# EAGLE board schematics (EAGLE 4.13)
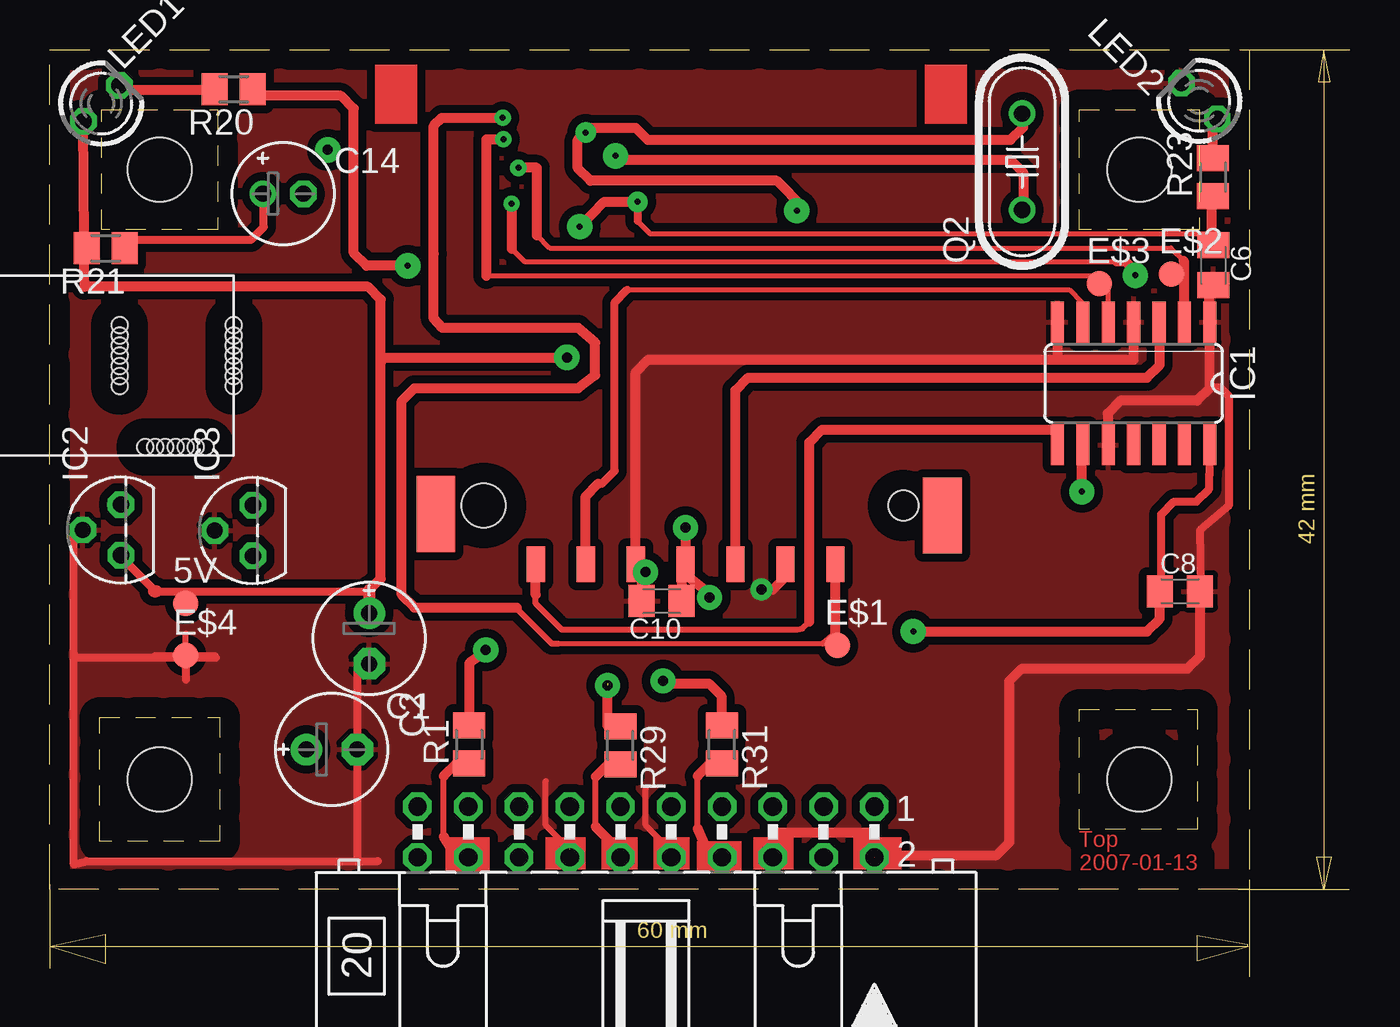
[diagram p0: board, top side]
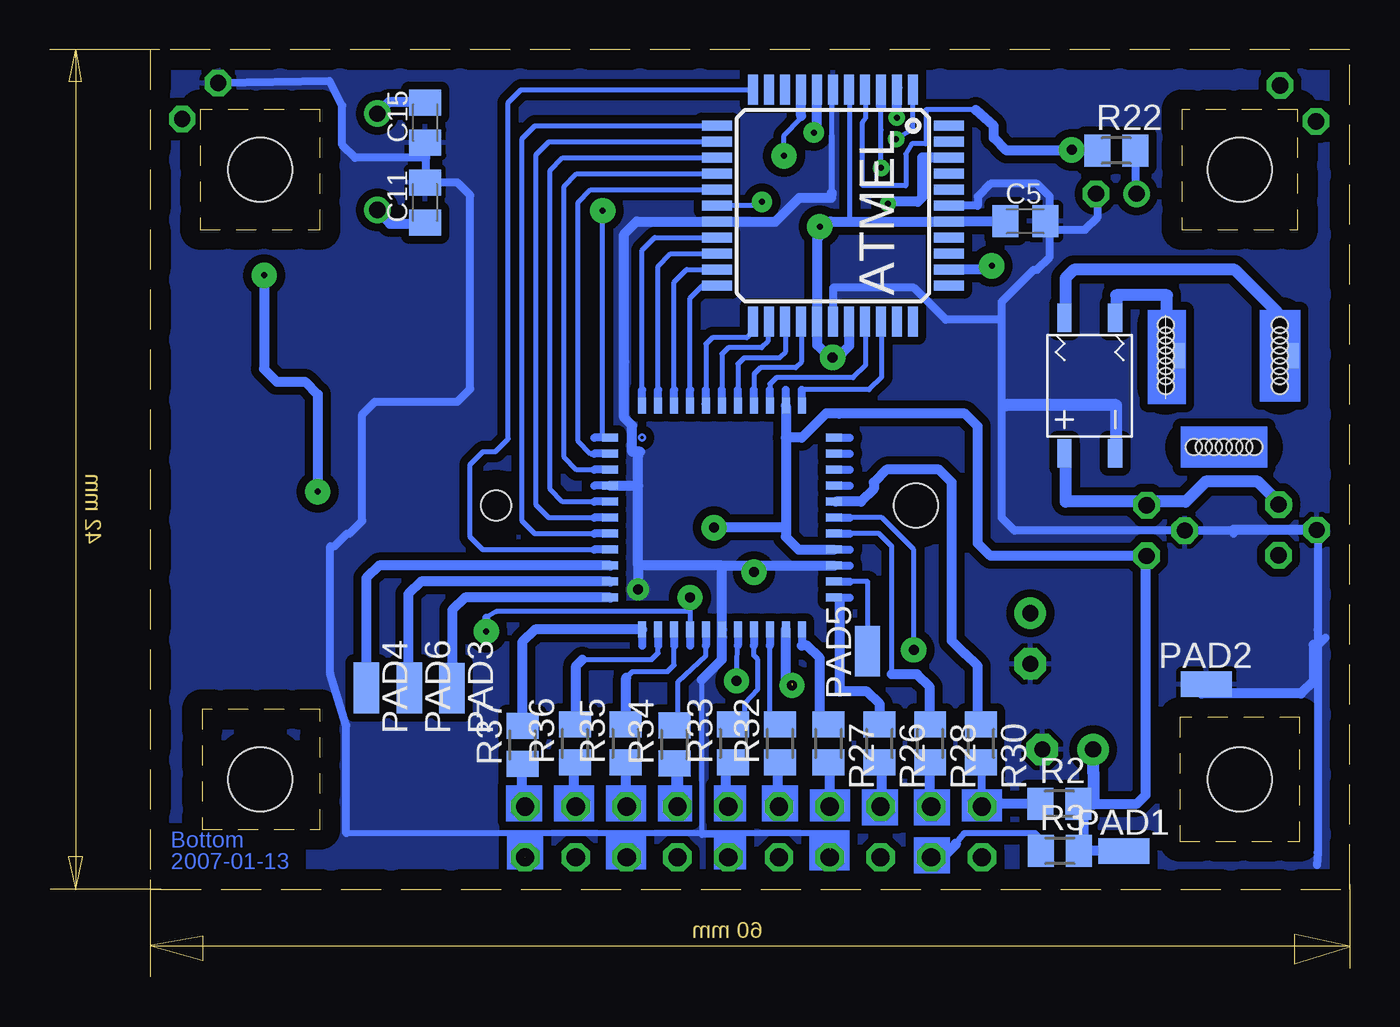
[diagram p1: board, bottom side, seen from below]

Size 65.03 x 46.38 mm. Coordinates in mm from the lower left corner, seen from the top.
Outline: 50 segments
Copper layers (1*16): Top 0.035mm / dielectric 1.5mm / Bottom 0.035mm
Design rules "default": minimum track width 10mil, minimum drill 24mil, track to track 8mil, track to pad 8mil, pad to pad 8mil, via to via 8mil, smd to smd 8mil, copper to edge 40mil, drill to drill 8mil, minimum pad ring 10mil, minimum via ring 8mil, stop-mask expansion 4mil, vias tented up to drill 0mil, thermal gap 10mil
Holes 3.2 mm at 5.5,40.38 54.5,40.38 54.5,9.88 5.5,9.88

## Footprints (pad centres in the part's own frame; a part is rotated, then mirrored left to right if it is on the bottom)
B1,27 = smd 1.27 x 1.27: PP 0,0
TQFP-44 = smd 1.5 x 0.5: 1 -5.8,4; 2 -5.8,3.2; 3 -5.8,2.4; 4 -5.8,1.6; 5 -5.8,0.8; 6 -5.8,0; 7 -5.8,-0.8; 8 -5.8,-1.6; 9 -5.8,-2.4; 10 -5.8,-3.2; 11 -5.8,-4; 23 5.8,-4; 24 5.8,-3.2; 25 5.8,-2.4; 26 5.8,-1.6; 27 5.8,-0.8; 28 5.8,0; 29 5.8,0.8; 30 5.8,1.6; 31 5.8,2.4; 32 5.8,3.2; 33 5.8,4 | smd 0.5 x 1.5: 12 -4,-5.8; 13 -3.2,-5.8; 14 -2.4,-5.8; 15 -1.6,-5.8; 16 -0.8,-5.8; 17 0,-5.8; 18 0.8,-5.8; 19 1.6,-5.8; 20 2.4,-5.8; 21 3.2,-5.8; 22 4,-5.8; 34 4,5.8; 35 3.2,5.8; 36 2.4,5.8; 37 1.6,5.8; 38 0.8,5.8; 39 0,5.8; 40 -0.8,5.8; 41 -1.6,5.8; 42 -2.4,5.8; 43 -3.2,5.8; 44 -4,5.8
E2,5-6E = drill 0.813 pad 1.575 round: + -1.27,0 | drill 0.813 pad 1.575 octagon: - 1.27,0
C0805K = smd 1.3 x 1.6: 1 -1,0; 2 1,0
E2-5 = drill 0.813 pad 1.27 round: + -1.016,0 | drill 0.813 pad 1.27 octagon: - 1.016,0
DC_CON = smd 1.27 x 0.635 bottom: IN 0,6.35; OUT 0,0.635 | hole 0.8: -0.508,0; -1.016,0; 0.508,0; 1.016,0; 1.524,0; -1.524,0; -0.508,5.715; -1.016,5.715; -1.524,5.715; 0.508,5.715; 1.016,5.715; 1.524,5.715; -4.572,3.937; -4.572,3.429; -4.572,4.445; -4.572,2.413; -4.572,1.905; -4.572,1.397; 0,5.715; -4.572,2.921; 0,0
SO14 = smd 0.66 x 2.032: 1 -3.81,-3.073; 2 -2.54,-3.073; 3 -1.27,-3.073; 4 0,-3.073; 5 1.27,-3.073; 6 2.54,-3.073; 7 3.81,-3.073; 8 3.81,3.073; 9 2.54,3.073; 10 1.27,3.073; 11 0,3.073; 12 -1.27,3.073; 13 -2.54,3.073; 14 -3.81,3.073
TO92 = drill 0.813 octagon: 1 -1.27,0; 2 0,1.905; 3 1.27,0
LED3MM = drill 0.813 octagon: A -1.27,0; K 1.27,0
MMC = smd 0.914 x 1.778: 3.3V 2,-25; CS -5.5,-25; GND -0.5,-25; GND1 7,-25; MISO 9.5,-25; MOSI -3,-25; SCK 4.5,-25 | smd 1.93 x 3.81: P$10 14.85,-22.57; P$11 -10.5,-22.5 | hole 2.2: -8.109,-22.071 | hole 1.5: 12.889,-22.071
SMD2 = smd 1.27 x 2.54: 1 0,0
HC49/S = drill 0.813 round: 1 -2.413,0; 2 2.413,0
M0805 = smd 1.3 x 1.6: 1 -0.95,0; 2 0.95,0
SMD_B40 = smd 1.422 x 0.711: + -3.387,1.27; - -3.387,-1.27; ~1 3.387,1.27; ~2 3.387,-1.27
ML20L = drill 0.914 octagon: 1 -11.43,-1.27; 2 -11.43,1.27; 3 -8.89,-1.27; 4 -8.89,1.27; 5 -6.35,-1.27; 6 -6.35,1.27; 7 -3.81,-1.27; 8 -3.81,1.27; 9 -1.27,-1.27; 10 -1.27,1.27; 11 1.27,-1.27; 12 1.27,1.27; 13 3.81,-1.27; 14 3.81,1.27; 15 6.35,-1.27; 16 6.35,1.27; 17 8.89,-1.27; 18 8.89,1.27; 19 11.43,-1.27; 20 11.43,1.27
VQ44 = smd 0.813 x 0.406: PIN$1 -5.6,4; PIN$2 -5.6,3.2; PIN$3 -5.6,2.4; PIN$4 -5.6,1.6; PIN$5 -5.6,0.8; PIN$6 -5.6,0; PIN$7 -5.6,-0.8; PIN$8 -5.6,-1.6; PIN$9 -5.6,-2.4; PIN$10 -5.6,-3.2; PIN$11 -5.6,-4; PIN$23 5.6,-4; PIN$24 5.6,-3.2; PIN$25 5.6,-2.4; PIN$26 5.6,-1.6; PIN$27 5.6,-0.8; PIN$28 5.6,0; PIN$29 5.6,0.8; PIN$30 5.6,1.6; PIN$31 5.6,2.4; PIN$32 5.6,3.2; PIN$33 5.6,4 | smd 0.406 x 0.813: PIN$12 -4,-5.6; PIN$13 -3.2,-5.6; PIN$14 -2.4,-5.6; PIN$15 -1.6,-5.6; PIN$16 -0.8,-5.6; PIN$17 0,-5.6; PIN$18 0.8,-5.6; PIN$19 1.6,-5.6; PIN$20 2.4,-5.6; PIN$21 3.2,-5.6; PIN$22 4,-5.6; PIN$34 4,5.6; PIN$35 3.2,5.6; PIN$36 2.4,5.6; PIN$37 1.6,5.6; PIN$38 0.8,5.6; PIN$39 0,5.6; PIN$40 -0.8,5.6; PIN$41 -1.6,5.6; PIN$42 -2.4,5.6; PIN$43 -3.2,5.6; PIN$44 -4,5.6

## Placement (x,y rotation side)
5V  [B1,27]  6.8,18.67 0 top
ATMEL  ATMEGA16-16AI  [TQFP-44]  25.84,38.59 270 bottom
C1  10 uF  [E2,5-6E]  14.1,11.37 0 top
C2  10 uF  [E2,5-6E]  15.97,16.92 270 top
C5  100 nF  [C0805K]  16.22,37.8 0 bottom
C6  100 nF  [C0805K]  58.22,35.6 270 top
C8  100 nF  [C0805K]  56.54,19.28 0 top
C10  100 nF  [C0805K]  30.6,18.8 180 top
C11  22 pF  [C0805K]  46.26,38.73 90 bottom
C14  10 uF  [E2-5]  11.67,39.18 0 top
C15  22 pF  [C0805K]  46.25,42.73 90 bottom
E$1  [B1,27]  39.4,16.58 0 top
E$2  [B1,27]  56.12,35.16 0 top
E$3  [B1,27]  52.5,34.67 0 top
E$4  [B1,27]  6.8,16.08 0 top
E$5  [DC_CON]  9.2,31.08 90 top
IC1  74LV125  [SO14]  54.22,29.69 180 top
IC2  LP2950 CZ-5.0  [TO92]  3.55,22.35 90 top
IC3  LP2950 CZ-3.3  [TO92]  10.15,22.33 90 top
LED1  [LED3MM]  2.57,43.7 45 top
LED2  [LED3MM]  57.51,43.82 135 top
MMC  [MMC]  29.8,45.65 0 top
PAD1  [SMD2]  11.29,6.29 270 bottom
PAD2  [SMD2]  7.17,14.63 270 bottom
PAD3  [SMD2]  44.91,14.44 180 bottom
PAD4  [SMD2]  49.19,14.46 180 bottom
PAD5  [SMD2]  24.12,16.28 0 bottom
PAD6  [SMD2]  47.05,14.45 180 bottom
Q2  16 MHz  [HC49/S]  48.65,40.78 90 top
R1  47  [M0805]  20.98,11.62 90 top
R2  10 k  [M0805]  14.51,8.66 0 bottom
R3  10 k  [M0805]  14.49,6.3 0 bottom
R20  120  [M0805]  9.19,44.41 180 top
R21  10k  [M0805]  2.78,36.45 180 top
R22  100  [M0805]  11.67,41.34 0 bottom
R23  1k8  [M0805]  58.19,40.01 90 top
R26  47  [M0805]  23.52,11.66 270 bottom
R27  47  [M0805]  26.06,11.66 270 bottom
R28  47  [M0805]  20.98,11.66 270 bottom
R29  47  [M0805]  28.54,11.59 270 top
R30  47  [M0805]  18.44,11.67 270 bottom
R31  47  [M0805]  33.62,11.62 270 top
R32  47  [M0805]  28.5,11.66 90 bottom
R33  47  [M0805]  30.84,11.67 90 bottom
R34  47  [M0805]  33.79,11.62 90 bottom
R35  47  [M0805]  36.22,11.67 90 bottom
R36  47  [M0805]  38.76,11.66 90 bottom
R37  47  [M0805]  41.38,11.6 90 bottom
RECT  [SMD_B40]  13,29.58 90 bottom
SV2  [ML20L]  29.82,7.24 180 top
XILINX  [VQ44]  31.4,22.98 0 bottom

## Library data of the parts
5V E$1-E$4 = testpad
ATMEL = Atmel_Prototype_Header
C1 C2 C5 C6 C8 C10 C11 C14 C15 R1-R3 R20-R23 R26-R37 = rcl
E$5 MMC RECT = jookie
IC1 = 74xx-eu
IC2 IC3 = linear
LED1 LED2 = led
PAD1-PAD6 = wirepad
Q2 = crystal
SV2 = con-harting-ml
XILINX = xilinx

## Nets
3.3V: C1.+ C8.1 C10.1 IC3.1 PAD1.1 R2.2 R3.2
5V: ATMEL.5 ATMEL.17 ATMEL.27 ATMEL.29 ATMEL.38 C2.+ C5.1 C6.1 LED1.A R21.2 R23.1
ACK: R1.2
AD0: R37.2
AD1: R36.2
AD2: R35.2
AD3: R34.2
AD4: R28.1
AD5: R26.1
AD6: R29.1
AD7: R32.2
CLK: ATMEL.7 C15.2 Q2.2
CS: IC1.8
CS1: ATMEL.42 IC1.9
DRQ: R31.1
GND: ATMEL.6 ATMEL.18 ATMEL.28 C1.- C2.- C5.2 C6.2 C8.2 C10.2 C11.2 C14.- C15.1 IC1.1 IC1.4 IC1.7 IC1.10 IC2.2 IC3.2 LED2.K PAD2.1 SV2.2 SV2.6 SV2.10 SV2.14
MISO: ATMEL.2
MOSI: IC1.6
MOSI1: ATMEL.1 IC1.5
N$1: ATMEL.35 R20.1
N$2: ATMEL.19
N$3: ATMEL.20
N$4: ATMEL.21
N$5: ATMEL.22
N$6: ATMEL.23
N$7: ATMEL.24
N$8: ATMEL.25
N$9: ATMEL.26
N$10: ATMEL.30
N$11: ATMEL.31
N$12: ATMEL.16
N$13: ATMEL.15
N$14: ATMEL.14
N$15: ATMEL.11
N$16: ATMEL.13
N$17: ATMEL.12
N$18: R27.2 SV2.13
N$19: R26.2 SV2.15
N$20: R28.2 SV2.17
N$21: R2.1 R30.2 SV2.19
N$22: R29.2 SV2.12
N$23: R31.2 SV2.8
N$24: R32.1 SV2.11
N$25: R33.1 SV2.9
N$26: R34.1 SV2.7
N$27: R35.1 SV2.5
N$28: R36.1 SV2.3
N$29: R37.1 SV2.1
N$31: ATMEL.10
N$32: ATMEL.9
N$33: C14.+ R21.1 R22.2
N$34: PAD3.1
N$35: PAD5.1
N$36: PAD4.1
N$37: PAD6.1
N$38: ATMEL.34
N$40: ATMEL.8 C11.1 Q2.1
N$44: LED2.A R23.2
N$47: LED1.K R20.2
N$50: R27.1
N$57: R1.1 R3.1 SV2.18
N$58: R30.1
N$61: ATMEL.39
RESET: ATMEL.4 R22.1
S$4: IC2.1
SCK: IC1.3
SCK1: ATMEL.3 IC1.2
URAW: IC2.3 IC3.3
VCC: IC1.14
WIREX: R33.2

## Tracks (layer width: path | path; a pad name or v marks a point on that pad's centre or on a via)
3.3V  (via drill 0.3 pad 1.27, 0.5 pad 0.41)
  Top 0.254: 31.8,20.59 31.83,20.59 31.83,20.58 31.6,20.58 | 33,19.17 v33,18.98 | 55.53,18.88 55.54,18.88 | 55.54,18.88 C8.1 55.6,19.28 | 55.54,18.88 55.73,18.88
  Top 0.406: 58.03,26.77 58.03,25.11 58,25.11 58,24.41 57.36,23.77 56.23,23.77 55.6,23.14 55.6,19.28
  Top 0.5: v31.8,22.48 31.8,20.59 | 31.83,20.59 32,19.98 33,19.17 33,18.88 | v43.2,17.27 54.89,17.27 55.53,17.91 55.53,18.88 | 31.6,20.58 C10.1
  Bottom 0.254: 28.2,26.98 28.2,28.58 28.19,28.56 28.2,28.56 | 25.8,21.38 25.8,21.37 25.79,21.37 | 28.2,22.58 28.2,22.48 | 33,17.37 33,16.98 | 33,17.37 32.99,17.37 | v33,18.98 33,18.27 | 33,18.27 33,17.37 | 13.3,7.07 13.3,7.09 R3.2 | 13.3,8.66 R2.2 | PAD1.1 11,6.09 11.2,6.3 11,5.98 | 10.2,21.05 10.2,21.08 | 33,18.27 42.7,18.27 43.2,17.98 | v43.2,17.27 43.1,17.08
  Bottom 0.406: 43.2,17.98 v43.2,17.27
  Bottom 0.5: 10.2,21.05 IC3.1 | 10.2,21.05 17.97,21.05 18.6,21.69 18.6,27.54 19.23,28.17 25.54,28.17 26.19,28.19 27.4,26.98 28.2,26.98 | 28.2,28.56 28.2,22.58 28.2,22.01 27.56,21.38 25.8,21.38 | 28.2,22.48 v31.8,22.48 | 13.3,7.09 13.3,8.66 | 11.2,6.3 R3.2 | R2.2 12.8,8.66 10.64,8.66 10.2,9.09 10.2,21.05
  Bottom 0.61: 12.8,8.66 12.8,10.17 12.83,10.2 C1.+
5V  (via drill 0.3 pad 1.02, 0.3 pad 1.27, 0.5 pad 1.27)
  Top 0.254: R23.1 58.09,37.17 30.03,37.17 29.4,37.81 | 1.63,36.77 R21.2 | 1.63,36.77 1.5,36.77 | 1.7,36.77 1.63,36.77 | 16.55,30.72 16.57,30.99
  Top 0.305: 58.1,36.6 C6.1 | R23.1 58.1,39.06
  Top 0.406: v29.4,38.77 29.4,37.81 | 5.32,19.28 15.91,19.28 | 3.6,20.98 5.2,19.38 5.2,19.28
  Top 0.5: 58.1,39.06 58.1,36.6 | v29.4,38.77 27.73,38.77 27.1,38.14 v26.5,37.53 | LED1.A 1.7,36.77 1.7,35.16 1.74,34.52 15.91,34.52 16.55,33.89 16.55,30.72 16.55,19.92 16,19.37 15.91,19.28 | 16.57,30.99 v25.87,30.99
  Top 0.61: C2.+ 15.97,19.34 16,19.38 16,19.37 | 5.2,19.28 5.32,19.28
  Bottom 0.254: ATMEL.17 31.7,38.58 | ATMEL.17 | ATMEL.17 29.4,38.58 v29.4,38.77 | 20.15,37.78 20.15,37.75 | 20.15,37.78 20.15,37.8 | ATMEL.5 25,44.34 25,37.78 24.6,37.77 | ATMEL.38 20.15,37.78 | 26.63,36.92 26.6,37.38 | 26.6,32.58 26.63,32.55 ATMEL.27 | 25,32.88 ATMEL.29 | 25.6,30.98 25.6,30.72 v25.87,30.99
  Bottom 0.5: 20.15,37.8 C5.1 | ATMEL.38 25,37.78 25.97,37.78 26.63,36.92 26.63,32.55 26.63,31.6 25.97,30.98 25.6,30.98 25.03,31.58 ATMEL.29 | 26.6,37.38 v26.5,37.53
ACK  (via drill 0.5 pad 1.27)
  Top 0.254: R1.2 21,12.56
  Top 0.5: 21,12.56 21,15.72 21.65,16.16 v21.8,16.35
  Bottom 0.254: v21.8,16.35 21.8,21.38 23.4,22.98 25.8,22.98 25.8,22.97 25.79,22.97
AD0
  Bottom 0.406: 41.4,12.55 R37.2 | 35.4,17.38 35.4,17.37 35.39,17.37
  Bottom 0.5: 41.4,12.55 41.4,16.74 40.77,17.38 35.4,17.38
AD1
  Bottom 0.254: 34.59,17.37 34.6,17.37 34.6,16.19 34.92,15.88 38.38,15.88 | 38.7,12.48 38.7,12.62 R36.2
  Bottom 0.5: 38.38,15.88 38.7,15.56 38.7,12.62
AD2
  Bottom 0.254: R35.2 36.2,12.62 | 33.8,17.37 33.8,17.38 | 33.8,17.37 33.79,17.37 | 36.2,14.96 35.88,15.27 34.12,15.27 33.8,15.59 33.8,17.37
  Bottom 0.5: 36.2,12.62 36.2,14.96
AD3
  Bottom 0.254: R34.2 33.6,12.57 33.6,14.77 32.2,16.08 32.2,17.37 32.19,17.37
AD4
  Bottom 0.254: R28.1 21,12.62 | 25.79,22.16 25.5,22.16 25.5,22.17 23.53,22.17 22.9,21.54 22.9,15.13
  Bottom 0.5: 21,12.62 21,14.5 21.63,15.13 22.9,15.13
AD5
  Bottom 0.254: R26.1 23.5,12.62 | 25.5,18.98 25.5,18.91 25.79,18.97
  Bottom 0.5: 23.5,12.62 23.5,13.64 24.13,14.27 25.5,14.27 25.5,18.91
AD6  (1 unrouted)
  Top 0.254: 27.9,12.53 R29.1
  Top 0.5: 27.9,12.53 27.9,14.67
  Bottom 0.254: 28.2,17.48 28.2,17.37 28.19,17.37 | 27.9,14.58 28.2,14.58
  Bottom 0.5: 28.2,14.58 28.2,17.37
AD7
  Bottom 0.254: 28.99,17.37 29,17.37 29,12.62 R32.2
CLK  (via drill 0.3 pad 1.02, 0.3 pad 1.27, 0.5 pad 1.27)
  Top 0.254: 26.41,41.88 v26.81,42.25 | 48.7,43.17 v48.65,43.17 Q2.2
  Top 0.5: 48.7,43.17 48.7,42.51 48.06,41.88 29.9,41.88 29.3,42.47 27,42.47 26.41,41.88 26.41,40.46 27.05,39.83 36.37,39.83 37.72,38.47 v37.37,38.34
  Bottom 0.254: 46.25,43.78 C15.2 | v26.81,42.25 26.64,42.14 | ATMEL.7 26.64,44.28 26.6,44.28 | 36.99,26.97 36.99,26.91 37.37,26.91 v37.37,38.34
  Bottom 0.5: Q2.2 48.06,43.78 46.25,43.78 | 26.64,42.14 26.64,44.28
CS
  Top 0.254: 24.3,20.67 24.3,20.59 24.33,20.59
  Top 0.305: 38,17.76 37.64,17.42 37.4,17.38 25.6,17.38 24.3,18.67 24.3,19.11
  Top 0.5: IC1.8 50.43,26.61 50.43,27.38 38.63,27.38 38,26.74 38,17.76 | 24.3,19.11 24.3,20.59
CS1  (via drill 0.3 pad 0.81, 0.3 pad 1.27)
  Top 0.254: 23.1,36.43 23.73,35.8 53.3,35.77 53.3,35.7 53.93,35.7
  Top 0.5: v23.1,38.69 23.1,36.43 | 53.93,35.7 v54.31,35.1 | IC1.9 51.63,26.61 v51.63,24.27
  Bottom 0.254: 22.9,38.78 v23.1,38.69
  Bottom 0.5: ATMEL.42 21.39,40.98 21.39,38.98 21.6,38.77 23.2,38.77 22.9,38.78 | v54.31,35.1 54.31,30.41 53.67,29.77 52.27,29.77 51.63,29.14 v51.63,24.27 51.53,24.27
DRQ  (via drill 0.5 pad 1.27)
  Top 0.254: 33.6,12.56 R31.1 | v30.67,14.8 30.7,14.67
  Top 0.5: 33.6,12.56 33.6,14.04 32.97,14.67 30.7,14.67
  Bottom 0.254: 30.6,17.37 30.6,17.38 | 30.6,17.37 30.59,17.37 | v30.67,14.8 30.6,17.37
GND  (via drill 0.5 pad 1.1, 0.5 pad 1.27)  (2 unrouted)
  Top 0.254: 29.33,20.59 29.4,20.59 29.4,20.24 v29.8,20.24 | 36.8,20.59 36.83,20.59 | 36.2,5.68 36.2,5.88 | 41.24,7.21 41.3,5.48 41.3,6.42 41.3,5.98 | IC1.1 | 52.93,26.38 52.93,26.5 52.93,26.61 IC1.10 | 50.43,32.76 IC1.7 | 54.23,30.88 50.43,30.88 | IC1.4 | 29.3,20.48 29.3,20.59 29.33,20.59 | 29.6,20.67 29.33,20.67 29.33,20.59 | 57.6,19.38 57.6,19.28 C8.2
  Top 0.305: 58,32.27 58,32.76 IC1.1 | 58,34.6 C6.2 | 24.8,9.77 24.8,7.57 26,6.38 SV2.14 | 31,5.98 31,6.38 29.8,7.57 29.8,9.38 | 6.8,15.98 6.8,17.17 | 5.2,16.08 8.3,16.08 8.3,15.98
  Top 0.406: 58.03,29.46 58,29.46 58,29.48 58.56,29.48 59,29.04 59,23.61 57.56,22.38 57.6,19.38 | 31,5.98 31,5.97 | 31,5.97 SV2.10 | 31.1,5.57 31,5.57 31,5.97 | 41.31,6.07 41.31,6.08 | 36.2,5.98 36.2,5.97 SV2.6 | 15.4,5.77 1.84,5.77 1.2,5.61 1.2,16.17 | 15.4,5.77 16.4,5.77 | IC2.2 1.22,22.35 1.2,22.38 1.2,16.17 | 6.8,15.98 1.2,15.98 1.2,16.17 | 6.8,15.98 8.3,15.98 | 6.8,15.98 6.8,14.88 | C2.- 15.4,15.65 15.4,11.37 | 15.4,11.37 C1.- | 15.4,5.77 15.4,11.37
  Top 0.5: v35.6,19.38 36.16,19.38 36.8,20.01 36.8,20.59 | 52.93,26.65 52.93,26.5 | 36.2,5.98 36.2,5.68 36.24,7.21 41.24,7.21 41.3,6.42 41.3,6.02 | 52.93,26.65 52.93,26.61 | 52.93,26.65 52.93,28.19 53.56,28.83 57.39,28.83 58.03,29.46 IC1.1 | 50.43,30.88 50.43,32.76 | IC1.4 54.23,30.88 29.94,30.88 29.3,30.24 29.3,20.59 | 29.6,20.67 C10.2 | 58,32.76 58,34.6 | 41.3,6.02 41.3,6.07 | 41.3,6.02 SV2.2 | 41.3,6.07 41.25,6.07 | 41.3,6.07 41.31,6.07 47.37,6.07 48,6.71 48,14.79 48.63,15.42 56.92,15.42 57.55,16.06 C8.2
  Top 0.61: 52.93,26.5 52.97,26.52 52.95,26.55 IC1.10 | C8.2 57.55,19.52
  Bottom 0.254: 31.11,7.06 32.4,7.06 32.4,14.88 | 31.4,16.98 31.39,16.98 | 31.4,18.98 31.4,17.38 31.39,17.37 31.4,17.37 | v29.8,20.24 29.8,20.58 30.72,20.58 30.72,20.56 30.72,20.55 | 7.4,14.38 7.5,14.38 7.5,14.63 PAD2.1 | ATMEL.18 | 36.3,30.77 36.3,30.72 | 36.99,24.56 36.99,24.58 35.6,24.58 | 35.6,26.08 35.5,26.08 35.5,26.27 | ATMEL.6 25.9,44.38 25.9,42.08
  Bottom 0.305: 25.9,39.21 25.9,42.08 | 31.2,7.18 26.8,7.18 26.01,6.39 SV2.14 | 31.2,7.18 31.2,6.18 | 31.2,7.18 36.2,7.18 | 36.2,7.18 36.2,5.77 | 36.2,7.18 41.2,7.18 | 41.2,7.18 41.2,5.98 | 41.2,7.18 50.2,7.18
  Bottom 0.406: 5.8,22.33 5.8,22.17 | 5.8,22.33 IC3.2 | 5.8,22.35 5.8,22.33 | 7.4,14.17 7.4,14.38 | C14.- 12.6,39.18 12.6,38.01 13.23,37.38 15,37.38 | C5.2 15,37.8 15,37.38 | 15,37.38 15,36.01 15.64,35.38 15.8,35.38 17.4,33.77 17.4,32.88 | IC3.2 5.75,22.33 | IC3.2 16.77,22.33 17.4,22.96 17.4,32.88 | ATMEL.28 25.84,34.48 21.8,34.48 20.2,32.88 17.4,32.88 | 14.9,37.48 15,37.48 15,38.38 | 15,38.38 15,39.04 15.64,39.67 17.97,39.67 18.6,39.04 18.6,38.58 20.4,38.58 | 15,37.38 15,38.38 | LED2.K 51.03,44.82 50.4,43.59 50.4,41.61 49.77,40.98 46.2,40.98 46.2,41.73 | 46.2,41.73 46.2,41.78 | 46.2,41.73 C15.1 | 46.2,41.73 46.2,39.73 C11.2 44.63,39.73 44,39.1 44,29.41 44.63,28.77 48.77,28.77 49.4,28.14 49.4,22.81 50.03,22.17 50.17,22.17 50.8,21.54 51,21.54 51,15.17 50.2,12.58 50.2,7.18 | SV2.10 31,5.97 | 1.6,22.55 IC2.2 1.2,22.35 1.2,22.38 1.6,22.17 1.6,22.55 | 1.6,22.55 1.6,17.38 | 1.6,17.38 1.6,16.58 | 1.6,16.58 1.6,16.6 | 1.6,16.58 1.2,16.98 | 1.6,16.58 1.6,6.21 1.64,5.57 | 1.6,16.6 1.8,16.6 | 1.6,17.38 1.6,16.6
  Bottom 0.5: IC2.2 5.8,22.35 | 1.8,16.6 1.8,14.81 2.43,14.17 7.4,14.17 | SV2.10 31.11,7.06 | 32.4,14.88 31.4,15.88 31.4,16.98 | 31.39,16.98 31.39,17.37 | 31.4,17.37 31.4,18.98 31.4,20.58 | 36.99,24.56 35.6,24.56 35.6,20.58 | 31.4,20.58 30.72,20.58 | 35.6,20.58 v35.6,19.38 | 31.4,20.58 35.6,20.58 | 30.72,20.56 25.79,20.56 | ATMEL.18 35.66,37.79 36.3,37.15 36.3,30.77 36.3,27.98 35.9,27.58 35.9,26.27 35.5,26.27 | 35.6,24.58 35.6,26.08 | ATMEL.18 28.73,37.77 27.53,38.98 25.94,38.98 25.9,39.21
  Bottom 0.61: 11.67,26.06 11.67,28.6 17.17,28.6
  other vias: 41.25,5.98
  pour Bottom (isolate 0.406): 0.2,45.97 59.4,45.97 59.4,4.77 0.2,4.77
  pour Top (isolate 0.406): 0.2,46.17 59.6,46.17 59.6,4.77 0.2,4.77
MISO  (via drill 0.3 pad 0.81)
  Top 0.254: 39.3,20.59 39.33,20.59 | 25.44,16.67 38.66,16.67 | 19.2,36.17
  Top 0.305: 38.66,16.67 39.3,17.21 | 23.37,18.48 23.37,18.41 25.11,16.67 25.44,16.67
  Top 0.5: v22.66,42.98 19.61,42.98 19.2,42.58 19.2,36.17 19.2,32.92 19.62,32.46 26.42,32.46 27.28,31.73 27.28,30.1 26.42,29.45 18.23,29.45 17.6,28.81 17.6,19.11 18.23,18.48 23.37,18.48 | 39.3,17.21 39.3,20.59
  Bottom 0.254: 22.64,44.44 ATMEL.2
  Bottom 0.5: v22.66,42.98 22.64,43.73 22.63,44.56 22.64,44.44
MOSI
  Top 0.254: 51.63,32.76 51.63,33.74 51,34.38 28.88,34.38 | 26.8,20.38 26.8,20.59 26.83,20.59 | 27.44,24.67 27.62,24.67
  Top 0.406: 28.88,34.38 28.25,33.74 28.25,25.31 27.62,24.67
  Top 0.5: 51.63,32.76 IC1.6 | 27.44,24.67 26.8,24.04 26.8,20.59
MOSI1  (via drill 0.3 pad 0.81)
  Top 0.254: 21.84,35.08 52.3,35.08 52.93,34.44 52.93,32.76
  Top 0.5: 52.93,32.67 52.93,32.76 IC1.5 | v22.69,41.91 21.84,41.91 21.84,35.08
  Bottom 0.254: ATMEL.1 21.83,44.69 21.8,44.69 21.8,44.38 21.84,43.92 21.84,42.44 v22.69,41.91
N$1  (via drill 0.3 pad 1.27)
  Top 0.254: 10.14,44.08 R20.1
  Top 0.5: 10.14,44.08 14.57,44.08 15.2,43.44 15.2,36.21 15.84,35.58 v17.9,35.58
  Bottom 0.254: 20.2,35.38 ATMEL.35 | v17.9,35.58 17.9,35.38
  Bottom 0.5: 17.9,35.38 ATMEL.35
N$2
  Bottom 0.254: 35.39,28.56 35.4,28.56 35.4,36.35 34.77,36.98 ATMEL.19
N$3
  Bottom 0.254: 34.59,28.56 34.6,28.56 34.6,35.54 33.97,36.17 31.6,36.17 31.6,36.19 ATMEL.20
N$4
  Bottom 0.254: 33.79,28.56 33.8,28.56 33.8,34.75 33.16,35.38 ATMEL.21
N$5
  Bottom 0.254: 32.99,28.56 33,28.56 33,33.95 32.37,34.59 ATMEL.22
N$6
  Bottom 0.254: 32.2,28.67 32.19,28.67 32.19,28.56 | 32.2,28.67 32.2,31.66 31.88,31.98 30.16,31.98 29.84,32.29 ATMEL.23 | 32.2,28.67 32.3,28.67
  Bottom 0.406: 32.19,28.56 32.2,28.56
N$7
  Bottom 0.254: 31.4,28.56 31.4,31.16 31.08,31.48 29.42,31.48 29.1,31.79 29.1,32.27 29.04,32.27 | 29.04,32.27 29,32.27 | ATMEL.24 29.04,32.27
  Bottom 0.406: ATMEL.24 29,32.38 | 31.4,28.56 31.39,28.56
N$8
  Bottom 0.254: 30.59,28.56 30.59,28.58 30.6,28.58 30.6,30.66 30.28,30.98 28.52,30.98 28.2,31.29 28.2,32.38
  Bottom 0.406: 30.59,28.56 30.6,28.56 | 28.2,32.58 28.2,32.38 ATMEL.25
N$9
  Bottom 0.254: 29.79,28.56 29.79,30.16 29.47,30.48 27.72,30.48 27.4,30.79 27.4,32.38 27.44,32.38 ATMEL.26
N$10
  Bottom 0.254: 28.99,28.56 29,28.56 29,29.66 28.68,29.98 24.84,29.98 24.2,30.61 24.2,32.38 ATMEL.30
N$11
  Bottom 0.254: 27.39,28.56 27.4,28.56 27.4,29.38 24.03,29.38 23.4,30.01 23.4,32.38 | 23.4,32.38 23.4,32.58 | 23.4,32.38 ATMEL.31
N$12
  Bottom 0.254: ATMEL.16 32,39.38 37.97,39.38 38.6,38.74 38.6,26.8 37.97,26.16 36.99,26.16
N$13
  Bottom 0.254: ATMEL.15 31.8,40.19 31.8,40.17 38.66,40.17 39.3,39.54 39.3,26 38.66,25.37 36.99,25.37
N$14
  Bottom 0.254: ATMEL.14 31.7,40.98 39.37,40.98 40,40.34 40,24.4 39.37,23.77 36.99,23.77
N$15
  Bottom 0.254: 36.99,21.37 43.37,21.37 44,22 44,25.64 43.37,26.27 42.73,26.27 42.1,26.91 42.1,43.74 41.47,44.38 29.9,44.38 29.9,44.39 | 29.9,44.39 29.9,44.67 | 29.9,44.39 ATMEL.11
N$16
  Bottom 0.254: 31.7,41.78 31.7,41.88 | 31.7,41.78 ATMEL.13 | 36.99,22.97 40.06,22.97 40.7,23.6 40.7,41.14 40.06,41.78 31.7,41.78
N$17
  Bottom 0.254: ATMEL.12 31.5,42.58 40.77,42.58 41.4,41.94 41.4,22.8 40.77,22.16 36.99,22.16
N$18
  Bottom 0.406: 26,10.72 R27.2 | SV2.13 26,8.41
  Bottom 0.5: 26,8.41 26,10.72
N$19
  Bottom 0.406: 23.4,10.77 23.4,10.72 R26.2 | SV2.15 23.4,8.41
  Bottom 0.5: 23.4,8.41 23.4,10.72
N$20
  Bottom 0.406: 21,10.77 21,10.72 R28.2 | SV2.17 21,8.41
  Bottom 0.5: 21,8.41 21,10.72
N$21
  Bottom 0.406: 18.4,10.72 18.4,10.77 | 18.4,10.72 R30.2 | 18.4,8.41 SV2.19 | 18.4,8.88 18.4,10.72
  Bottom 0.5: 18.4,8.66 18.4,8.41 | R2.1 18.4,8.66 | 18.4,8.66 18.4,8.88
N$22
  Top 0.254: 28.5,5.87 28.5,5.77 | 28.5,5.87 SV2.12 | 28.5,5.88 28.5,5.87
  Top 0.305: 27.3,7.51 27.3,10
  Top 0.5: R29.2 27.94,10.63 27.3,10 | 27.3,7.51 28.13,6.68 28.5,5.88
N$23
  Top 0.254: 33.6,10.67 33.6,10.66 R31.2
  Top 0.305: 32.4,7.41 32.4,10.04
  Top 0.5: SV2.8 33.03,5.97 32.4,7.41 | 32.4,10.04 33.03,10.67 33.6,10.67
N$24
  Bottom 0.254: SV2.11 28.6,8.41 | 28.6,10.72 R32.1
  Bottom 0.5: 28.6,8.41 28.6,10.72
N$25
  Bottom 0.406: 31.2,10.77 31.2,10.72 R33.1 | SV2.9 31.2,8.41
  Bottom 0.5: 31.2,8.41 31.2,10.72
N$26
  Bottom 0.61: R34.1 | R34.1 | SV2.7 33.63,10.51 R34.1
N$27
  Bottom 0.406: 36.2,10.77 36.2,10.72 R35.1 | SV2.5 36.2,8.41
  Bottom 0.5: 36.2,8.41 36.2,10.72
N$28
  Bottom 0.406: 38.8,10.77 38.8,10.72 R36.1 | SV2.3 38.8,8.41
  Bottom 0.5: 38.8,8.41 38.8,10.72
N$29
  Bottom 0.406: 41.4,10.65 R37.1 | SV2.1 41.4,8.41
  Bottom 0.5: 41.4,8.41 41.4,10.65
N$33  (via drill 0.7 pad 1.27)
  Top 0.254: R21.1 3.73,36.88 | v10.65,39.17 10.6,39.17 | v10.65,39.17 C14.+ | 10.7,39.17 v10.65,39.17
  Top 0.406: 3.73,36.88 10.07,36.88 10.7,37.51 10.7,39.17
  Bottom 0.254: 10.7,41.38 10.7,41.34 R22.2 | C14.+ 10.7,39.18
  Bottom 0.406: 10.7,39.18 10.7,41.34
N$34
  Bottom 0.254: 36.99,18.98 36.99,18.97 | PAD3.1
  Bottom 0.5: 36.99,18.98 44.27,18.98 44.9,18.34 PAD3.1
N$35
  Bottom 0.254: PAD5.1 24.1,16.3 24.1,19.77 25.8,19.77 25.79,19.77
N$36
  Bottom 0.254: 36.99,20.58 36.99,20.56 | PAD4.1
  Bottom 0.5: 36.99,20.58 48.56,20.58 49.2,19.94 PAD4.1
N$37
  Bottom 0.254: 36.99,19.77 | 47.1,14.38 47.1,14.45 PAD6.1
  Bottom 0.5: 36.99,19.77 46.47,19.77 47.1,19.14 47.1,14.45
N$39  (via drill 0.5 pad 1.27)
  other vias: 29.8,20.24
N$40  (via drill 0.3 pad 1.27)
  Top 0.254: 48.7,38.27 48.65,38.27 Q2.1
  Top 0.5: 28.7,40.88 v28.3,41.08 | 28.1,40.88 28.7,40.88 | 28.7,40.88 48.06,40.88 48.7,40.24 48.7,38.27
  Bottom 0.254: 46.26,37.67 C11.1 | v28.3,41.08 28.3,42.09 27.44,42.95 27.44,43.08
  Bottom 0.5: Q2.1 48.65,38.31 48.01,37.67 46.26,37.67 | 27.44,43.08 ATMEL.8
N$41
  Bottom 0.406: 8.6,31.49 8.54,31.49
N$44
  Top 0.254: 58.38,42.88 58.4,42.88 | 58.38,42.88 LED2.A | 58.19,42.88 58.38,42.88
  Top 0.5: R23.2 58.19,42.88
N$47
  Top 0.254: 8.5,43.97 8.44,44.38 R20.2 | LED1.K 3.64,44.38
  Top 0.5: 3.64,44.38 8.44,44.38
N$48
  Bottom 0.305: 28.23,44.58 28.2,44.58
N$50
  Bottom 0.254: R27.1 26.5,12.63 | 27.39,17.37 27.4,17.37 27.4,16.58
  Bottom 0.5: 26.5,12.63 26.5,15.94 27.14,16.58 27.4,16.58
N$57
  Top 0.254: 21,10.67 21,10.66 R1.1
  Top 0.305: 19.7,7.01 19.7,10.04
  Top 0.5: SV2.18 20.34,5.97 19.7,7.01 | 19.7,10.04 20.34,10.67 21,10.67
  Bottom 0.254: SV2.18 20.9,5.87 20.9,5.98
  Bottom 0.305: R3.1 15.48,6.89 15.72,7.18 19.29,7.18 19.7,6.66
  Bottom 0.5: 20.9,5.87 20.9,5.77 | 19.7,6.66 19.7,6.61 20.34,5.98 20.9,5.98
N$58
  Bottom 0.254: R30.1 18.6,12.62 | 25.5,23.77 25.79,23.77 25.7,23.77
  Bottom 0.5: 18.6,12.62 18.6,15.54 19.23,16.17 19.27,16.17 19.9,16.81 19.9,24.74 20.53,25.38 23.16,25.38 23.8,24.74 23.8,24.41 24.44,23.77 25.7,23.77
N$59  (via drill 0.5 pad 1.27)
  other vias: 27.9,14.58
N$62  (via drill 0.5 pad 1.27)
  other vias: 31.8,22.48
N$63  (via drill 0.5 pad 1.27)
  other vias: 33,18.98
N$72  (via drill 0.5 pad 1.27)
  other vias: 3.5,23.62
N$76  (via drill 0.7 pad 1.27)
  other vias: 12.7,39.17
N$79  (via drill 0.5 pad 1.27)
  other vias: 48.65,38.38
RESET  (via drill 0.5 pad 1.27)
  Bottom 0.254: 18.7,43.38 21.2,43.38 21.2,41.67 21.9,41.67 22.2,41.17 22.2,39.58 24.37,39.58 24.37,42.75 24.2,42.98 24.2,44.38 ATMEL.4
  Bottom 0.406: R22.1 12.6,41.34 12.6,41.38 v13.9,41.38
  Bottom 0.5: R22.1 17.16,41.34 17.8,41.97 17.8,42.58 18.7,43.38
S$1
  Bottom 0.61: 9,31.77 9.13,31.77 9.13,34.1 11.67,34.1 11.67,33.26
S$2
  Bottom 0.406: 6,26.17 5.8,26.17
S$3
  Bottom 0.61: 14.21,32.83 14.21,34.95 13.79,35.37 5.74,35.37 3.63,33.26
SCK
  Top 0.254: 34.3,20.59 34.33,20.59
  Top 0.5: IC1.3 55.53,32.76 55.53,30.61 54.89,29.98 34.94,29.98 34.3,29.34 34.3,20.59
SCK1  (via drill 0.3 pad 0.81)
  Top 0.254: 24.37,37.1 25.01,36.47 56.09,36.47 56.73,35.83
  Top 0.5: v23.44,40.48 24.37,40.48 24.37,37.1 | 56.73,32.76 56.73,32.58 | 56.73,32.76 IC1.2 | 56.73,35.83 56.73,32.76
  Bottom 0.254: 23.44,44.4 ATMEL.3 | 23.44,43.54 23.44,42.38 v23.44,40.48
  Bottom 0.5: 23.44,43.54 23.44,44.4
URAW
  Bottom 0.61: IC2.3 3.55,23.73 4.6,24.77 7.2,24.77 8.2,23.77 10.2,23.77 | 10.2,23.77 10.15,23.73 IC3.3 | 10.2,23.77 14.2,23.77 14.2,26.58
WIREX
  Bottom 0.254: R33.2 30.9,12.62 30.9,13.14 30.27,12.85 30.25,13.67 29.6,14.38 29.6,15.88 29.8,16.08 29.79,17.37
(copper drawn outside any net)
  shapes: Bottom area x17, Top area x7

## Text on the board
Top: Top | 2007-01-13
Bottom: Bottom | 2007-01-13
Dimension: 42 mm | 60 mm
